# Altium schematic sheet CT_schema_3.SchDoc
size 258 x 163 mm
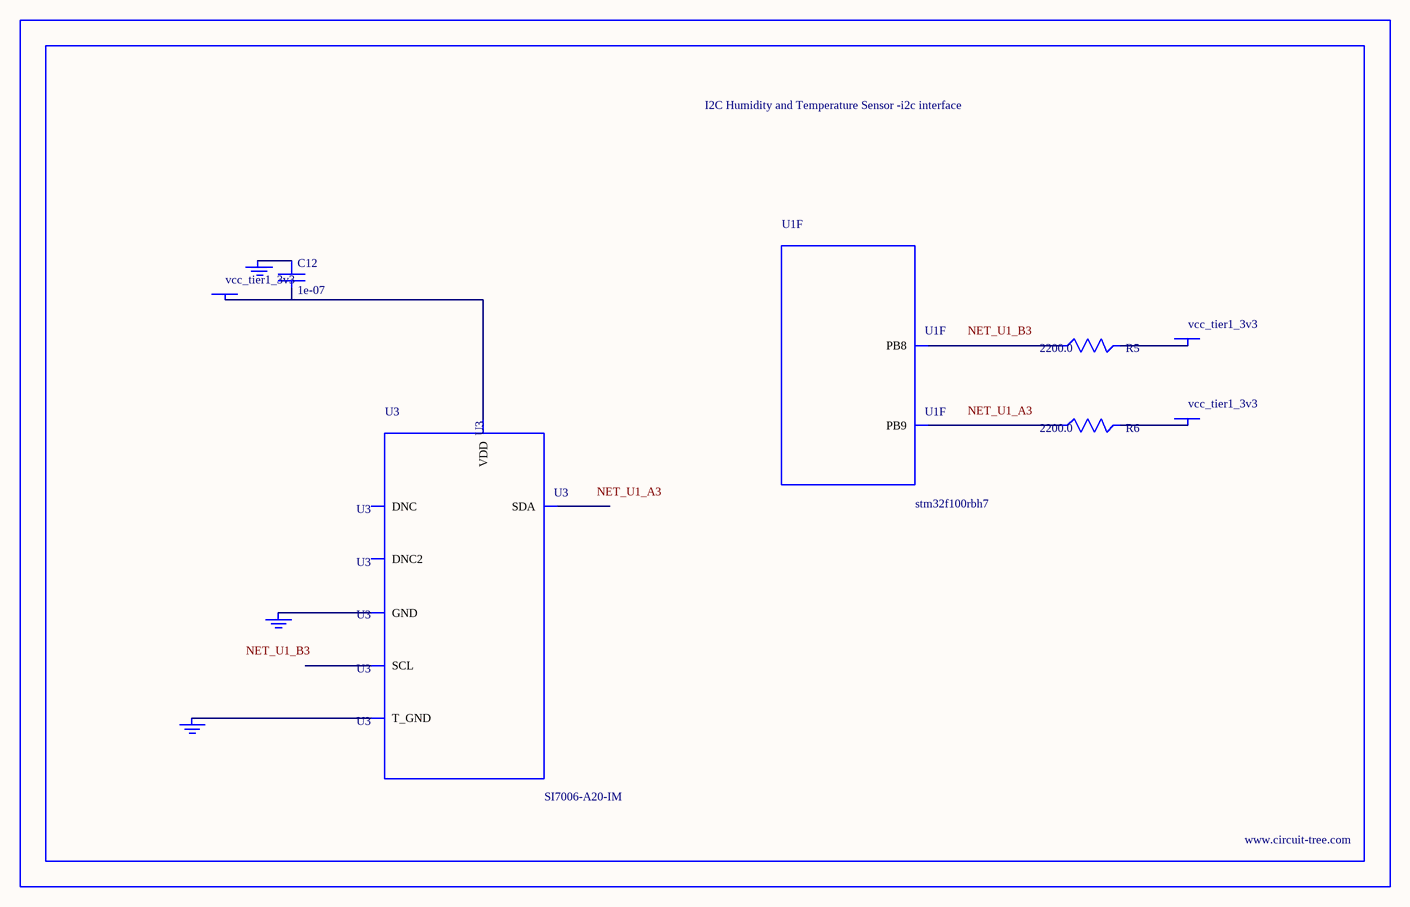
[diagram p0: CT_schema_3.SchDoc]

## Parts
BORDER2  (no value)
C12  1e-07  [C0402]
GND_INSTANCE_2_0  (no value)
GND_INSTANCE_2_1  (no value)
GND_INSTANCE_2_2  (no value)
POWER_INSTANCE_2_0  vcc_tier1_3v3
POWER_INSTANCE_2_1  vcc_tier1_3v3
POWER_INSTANCE_2_2  vcc_tier1_3v3
R5  2200.0  [R0603]
R6  2200.0  [R0603]
U1  stm32f100rbh7  [TFBGA64]  (part F of 6)
U3  SI7006-A20-IM  [DFN-6]

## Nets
NetC12_1: C12.1 GND_INSTANCE_2_0.0(GND)
NetC12_2: C12.2 POWER_INSTANCE_2_0.0(PWR) U3.5(VDD)
NetGND_INSTANCE_2_1_0: GND_INSTANCE_2_1.0(GND) U3.7(T_GND)
NetGND_INSTANCE_2_2_0: GND_INSTANCE_2_2.0(GND) U3.2(GND)
NetPOWER_INSTANCE_2_1_0: POWER_INSTANCE_2_1.0(PWR) R5.2
NetPOWER_INSTANCE_2_2_0: POWER_INSTANCE_2_2.0(PWR) R6.2
NetR5_1: R5.1 U1.B3(PB8)
NetR6_1: R6.1 U1.A3(PB9)

Not connected (* = marked no-connect by the designer): U3 1(SDA) 3(DNC) 4(DNC2) 6(SCL)

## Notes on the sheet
- Labels drawn without touching a wire or pin: NET_U1_A3, NET_U1_B3

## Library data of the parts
BORDER2 = BORDER_PAGE2
C12 = C0402C104K3RACTU
GND_INSTANCE_2_0-GND_INSTANCE_2_2 = GND
POWER_INSTANCE_2_0-POWER_INSTANCE_2_2 = PWR
R5 R6 = RC0603JR-072K2L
